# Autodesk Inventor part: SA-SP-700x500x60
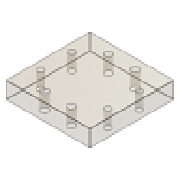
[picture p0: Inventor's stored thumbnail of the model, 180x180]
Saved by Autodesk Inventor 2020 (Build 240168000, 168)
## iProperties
Created: 2019-01
Part Number: SA-SP-700x500x60
Material: S 55 C
Description: Support Plate
Document SubType Name: Modeling
Designer: LENOVO-CADCIM
Standard Revision: 1
Manufacturer: FUTABA
Language: en-US
Size Designation: 700x500x60
Categories: <MemberInstance><Categories><Category DisplayName="Mold" InternalName="349578f2-f4d4-4954-8c09-8e99297a61c0" Mnemonic="MOLD"><Category DisplayName="Mold Plates"
Density: 7.85 g/cm^3
Appearance: Polycarbonate - Smoked
IsCustomPart: 1
Author: LENOVO-CADCIM
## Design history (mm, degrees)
sketch "Sketch1"
  geometry: L1 (-250, 350)-(250, 350); L2 (250, 350)-(250, -350); L3 (250, -350)-(-250, -350); L4 (-250, -350)-(-250, 350); 5 further points
  constraints: 8 end point, 2 midpoint, 2 parallel, 1 horizontal, 1 horizontal alignment, 1 perpendicular, 1 vertical alignment
  dimensions: "d68" = 500 distance between parallel lines of L2 L4 (= W_); "d69" = 700 distance between parallel lines of L3 L1 (= L); "d70" = 317 vertical distance of point (0, 0) point (-128, 317) (= 0.5 x RP_L); "d71" = 128 horizontal distance of point (0, 0) point (-128, 317) (= 0.5 x RP_W); "d72" = 243 vertical distance of point (0, 0) point (-205, 243) (= 0.5 x S1_L); "d73" = 205 horizontal distance of point (0, 0) point (-205, 243) (= 0.5 x S1_W)
extrude "Extrusion1" new body sketch "Sketch1" distance "d20" = 60 (= H_); taper "d30" = 0 deg
body "Solid1"
hole "Hole1" sketch "Sketch1" diameter "d74" = 18 (= S1_d1); stored, may be unused: countersink angle "d78" = 90 deg, drill point angle "d80" = 0 deg; dims "d75" = 6, "d76" = 4, "d77" = 2, "d79" = 60 (= H_)
pattern_linear "Rectangular Pattern1" dims "d102" = 243 (computed from S1_L, Ns), "d105" = 410 (computed from S1_W, Nw)
hole "Hole2" sketch "Sketch1" diameter "d81" = 31 (= RP_d1); stored, may be unused: countersink angle "d85" = 90 deg, drill point angle "d87" = 0 deg; dims "d82" = 6, "d83" = 4, "d84" = 2, "d86" = 60 (= H_)
pattern_linear "Rectangular Pattern2" dims "d108" = 634 (computed from RP_L, Nl), "d111" = 256 (computed from RP_W, Nw)
chamfer "Chamfer1" distance "d112" = 0.5; stored, may be unused: second distance "d113" = 2, angle "d114" = 45 deg
other parameters: "L" = 700 [user parameter; used in 1 equation term], "W_" = 500 [user parameter; used in 1 equation term], "H_" = 60 [user parameter; used in 3 equation terms], "RP_W" = 256 [user parameter; used in 2 equation terms], "S1_d1" = 18 [user parameter; used in 1 equation term], "RP_d1" = 31 [user parameter; used in 1 equation term], "S1_L" = 486 [user parameter; used in 2 equation terms], "RP_L" = 634 [user parameter; used in 2 equation terms]
